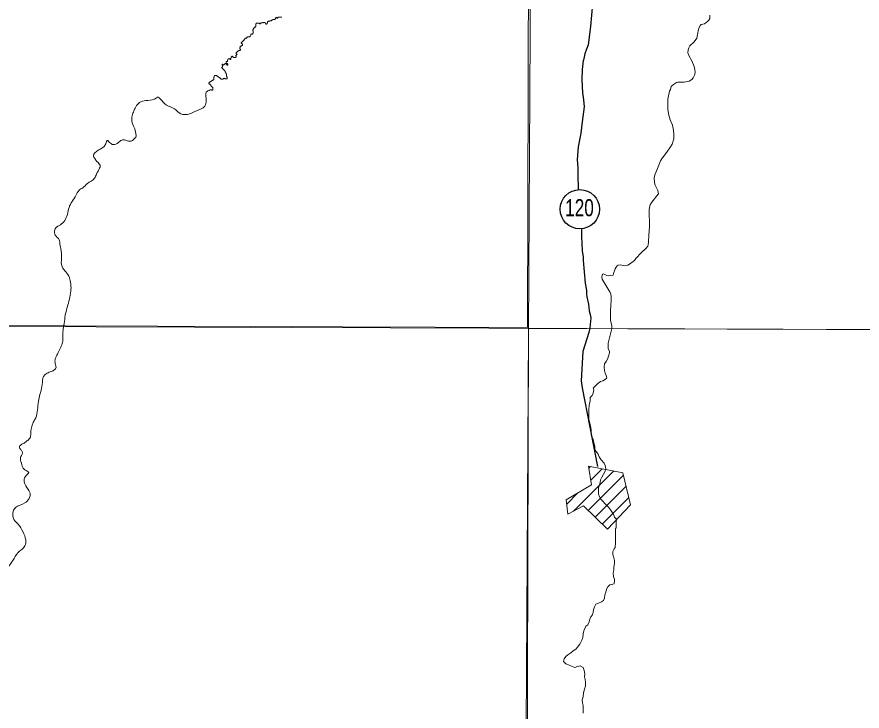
# Model space of a CAD drawing. Extents: x 553962 to 842807, y 8883888 to 9032388.
# Drawn here: x 605483 to 608938, y 8908325 to 8911165 of the extents above; entities that cross this region are included whole.
import ezdxf
from ezdxf.enums import TextEntityAlignment as Align

# ---------------------------------------------------------------- set-up
doc = ezdxf.new("R2010")
doc.units = 0
doc.header["$LTSCALE"] = 20
doc.layers.add('6', color=7, linetype='Continuous', lineweight=13)

msp = doc.modelspace()

# ---------------------------------------------------------------- linework, layer by layer
at = {"layer": '6'}
for p, q in [((574653.9, 8910009.29), (626625.69, 8909822.11)), ((607820.79, 8909318.7), (607828.11, 8909326.02)), ((607828.78, 8909270.13), (607875.43, 8909316.78)), ((607758.55, 8909143.32), (607922.76, 8909307.53)), ((607817.86, 8909146.06), (607962.46, 8909290.66)), ((607730.52, 8909171.86), (607776.5, 8909217.84)), ((607846.56, 8909118.2), (607973.3, 8909244.94)), ((607875.27, 8909090.34), (607984.15, 8909199.21))]:
    msp.add_line(p, q, dxfattribs=at)
for points in [[(607657.67, 8924743.35), (607574.22, 8909874.89), (607492.34, 8896026.67)], [(606523.31, 8911148.48), (606522.69, 8911148.69), (606521.67, 8911148.74), (606520.47, 8911148.8), (606519.25, 8911148.8), (606517.68, 8911148.53), (606516.48, 8911148.21), (606515.23, 8911147.91), (606513.83, 8911147.47), (606512.46, 8911147.32), (606510.89, 8911147.08), (606509.89, 8911146.46), (606508.86, 8911145.98)], [(606546.39, 8911159.84), (606543.77, 8911162.45), (606542.77, 8911162.38), (606541.9, 8911161.78), (606541.17, 8911160.88), (606540.7, 8911159.66), (606540.1, 8911158.26), (606539.45, 8911157.11), (606538.88, 8911156.06), (606538.33, 8911155.11), (606537.33, 8911154.64), (606536.23, 8911154.32), (606535.08, 8911154.32), (606533.88, 8911154.5), (606532.68, 8911154.21), (606531.49, 8911153.94), (606530.56, 8911153.41), (606529.59, 8911152.92), (606528.36, 8911152.97), (606526.87, 8911153.1), (606525.67, 8911153.11), (606524.94, 8911152.08), (606524.59, 8911151.11), (606524.17, 8911150.03), (606523.3, 8911148.48)], [(606565.15, 8911164.35), (606562.93, 8911163.56), (606559.98, 8911163.14), (606557.02, 8911163.14), (606553.16, 8911163.67), (606551.69, 8911163.82), (606550.56, 8911164.1), (606549.49, 8911164.1), (606549.29, 8911163), (606549.54, 8911161.9), (606549.79, 8911160.53), (606549.79, 8911159.48), (606548.84, 8911159), (606547.42, 8911159.41), (606546.39, 8911159.84)], [(608315.54, 8911171.73), (608315.61, 8911158.53), (608311.61, 8911151.94), (608307.35, 8911147.5), (608293.61, 8911136.89), (608279.96, 8911133.01), (608275.92, 8911129.45), (608268.82, 8911114.47), (608265.87, 8911093.15), (608261.93, 8911077.14), (608251.47, 8911062.72), (608234.36, 8911045.72), (608229.57, 8911037.8), (608226.74, 8911030.08), (608226.03, 8911018.33), (608229.52, 8911006.66), (608241.44, 8910984.96), (608251.55, 8910961.24), (608254.25, 8910949.42), (608255.3, 8910939.15), (608254.11, 8910930.39), (608252.74, 8910925.9), (608247.84, 8910915.8), (608242.31, 8910908.25), (608230.98, 8910902.21), (608210.39, 8910897.23), (608184.7, 8910897.91), (608178.91, 8910895.71), (608166.96, 8910888.78), (608158.11, 8910879.61), (608154.39, 8910868.28), (608151.07, 8910860.93), (608144.33, 8910828.85), (608143.31, 8910810.6), (608144.38, 8910797.99), (608143.86, 8910785.4), (608147.53, 8910763.33), (608153.66, 8910743.49), (608162.48, 8910721.36), (608166.26, 8910708.78), (608168.65, 8910688.23), (608168.26, 8910666.13), (608161.58, 8910644.74), (608155.1, 8910632.91), (608140.41, 8910611.88), (608121.6, 8910588.76), (608113.61, 8910576.05), (608102.12, 8910544.39), (608090.67, 8910519.25), (608088.69, 8910506.68), (608089.19, 8910486.11), (608091.86, 8910475.89), (608103.11, 8910454.43), (608105.72, 8910441.42), (608104.82, 8910439.14), (608078.56, 8910407.49), (608072.03, 8910396.61)], [(606478.63, 8911137.21), (606477.8, 8911136.54), (606476.1, 8911136.54), (606475.13, 8911136.85), (606474.48, 8911137.82), (606473.68, 8911138.48), (606472.66, 8911138.58), (606471.59, 8911138.58), (606470.49, 8911138.59), (606469.21, 8911138.47), (606468.04, 8911138.47), (606466.62, 8911138.48), (606465.27, 8911138.65), (606464.37, 8911139.36), (606463.22, 8911139.16), (606462.15, 8911138.69), (606461.12, 8911137.89), (606460.5, 8911136.95), (606460.3, 8911135.77), (606460.15, 8911134.3), (606460.15, 8911133.3), (606460.15, 8911132.3), (606460.15, 8911130.87), (606460, 8911129.07), (606459.7, 8911127.6), (606459.27, 8911126.57), (606458.82, 8911125.35), (606458.27, 8911124.3), (606457.32, 8911123.35), (606456.22, 8911122.41), (606455, 8911121.53), (606454.08, 8911120.76), (606453, 8911120.02), (606452.08, 8911119.57), (606451.2, 8911118.85), (606450.61, 8911117.92), (606449.58, 8911116.1), (606449.36, 8911115.13), (606448.76, 8911113.98), (606448.48, 8911112.88), (606448.16, 8911111.75), (606448.01, 8911110.56), (606448, 8911109.35), (606448, 8911108.18), (606448.1, 8911107.13), (606448.28, 8911106.08), (606448.33, 8911104.98), (606448.55, 8911103.63), (606448.8, 8911102.43), (606448.93, 8911101.35), (606448.97, 8911100.15), (606448.85, 8911098.2), (606448.5, 8911097.1), (606448.05, 8911096.18), (606447.3, 8911095.5), (606446.33, 8911095.03), (606445.03, 8911094.56), (606443.63, 8911094.57), (606442.63, 8911094.77), (606441.46, 8911094.65), (606440.23, 8911094.18), (606439.23, 8911093.53), (606438.73, 8911092.03), (606438.83, 8911090.88), (606437.66, 8911086.36)], [(606508.86, 8911145.98), (606508.11, 8911144.94), (606507.64, 8911143.76), (606507.51, 8911142.59), (606507.34, 8911141.36), (606506.96, 8911139.99), (606506.64, 8911138.62), (606506.51, 8911137.44), (606506.11, 8911136.49), (606505.39, 8911135.69), (606504.29, 8911135.2), (606503.19, 8911135.2), (606502.07, 8911135.53), (606501.17, 8911136.23), (606500.47, 8911137.11), (606499.75, 8911137.96), (606499.15, 8911138.79), (606498.4, 8911139.74), (606497.48, 8911140.57), (606496.63, 8911141.17), (606495.38, 8911141.75), (606494.21, 8911142.03), (606493.23, 8911142.41), (606492.03, 8911142.42), (606490.81, 8911142.24), (606489.61, 8911141.47), (606488.71, 8911140.78), (606487.71, 8911140.28), (606486.57, 8911140.33), (606485.29, 8911140.39), (606484.07, 8911140.44), (606482.9, 8911140.57), (606481.87, 8911140.45), (606480.45, 8911139.95), (606479.58, 8911139.41), (606479.13, 8911138.38), (606478.63, 8911137.21)], [(606437.66, 8911086.36), (606436.73, 8911085.74), (606435.71, 8911085.06), (606434.81, 8911084.34), (606433.89, 8911083.7), (606432.61, 8911083.1), (606431.22, 8911083), (606429.59, 8911082.81), (606428.37, 8911082.76), (606427, 8911082.72), (606425.52, 8911082.42), (606424.45, 8911082.08), (606423.53, 8911081.43), (606423.23, 8911080.43), (606423.1, 8911079.36), (606422.75, 8911078.18), (606422.05, 8911077.23), (606419.88, 8911077.27), (606417.17, 8911077.7), (606411.51, 8911071.74), (606411.19, 8911070.54), (606411.44, 8911069.57), (606410.74, 8911068.72), (606409.66, 8911068.2), (606408.64, 8911067.83), (606408.49, 8911066.73), (606406.72, 8911065.4)], [(606406.72, 8911065.4), (606400.11, 8911059.18), (606399.49, 8911057.18), (606401.77, 8911054.97), (606403.27, 8911054.79), (606404.42, 8911054.74), (606405.09, 8911053.78), (606405.44, 8911052.76), (606405.69, 8911051.63), (606405.64, 8911050.48), (606405.44, 8911049.31), (606404.84, 8911048.41), (606403.99, 8911047.84), (606403.19, 8911047.19), (606402.04, 8911046.89), (606400.94, 8911046.25), (606400.09, 8911045.55), (606399.22, 8911044.9), (606398.17, 8911045.05), (606397.15, 8911045.28), (606396.15, 8911044.64), (606395.7, 8911043.74), (606395.6, 8911042.51), (606395.5, 8911041.24), (606395.17, 8911039.69), (606395, 8911038.41), (606394.95, 8911036.91), (606394.94, 8911035.74), (606394.94, 8911034.71), (606395.62, 8911033.73), (606396.14, 8911032.86), (606396.49, 8911031.76), (606396.49, 8911030.71), (606396.49, 8911029.33), (606396.19, 8911028.16), (606395.54, 8911027.33), (606394.49, 8911027.14), (606393.42, 8911026.89), (606391.87, 8911026.72), (606390.8, 8911026.57), (606389.32, 8911026.33), (606388.2, 8911025.96), (606387.15, 8911025.31), (606386.03, 8911024.59), (606385.3, 8911023.57), (606384.58, 8911022.59), (606383.95, 8911021.7), (606383.08, 8911020.52), (606382.15, 8911019.83), (606381.23, 8911019.2), (606380.38, 8911018.43), (606379.78, 8911017.28), (606379.58, 8911015.88), (606379.73, 8911014.83), (606380.43, 8911013.48), (606381.4, 8911012.88), (606382.55, 8911012.77), (606383.25, 8911011.95), (606382.6, 8911011.1), (606381.78, 8911010.47), (606380.68, 8911010.13), (606379.78, 8911009.43), (606378.95, 8911008.51), (606378.65, 8911007.33), (606378.6, 8911006.11)], [(606344.24, 8910987.34), (606343.59, 8910982.87), (606342.52, 8910982.42), (606341.37, 8910982.53), (606341.09, 8910982.73), (606339.85, 8910982.58), (606338.8, 8910982.16), (606338.62, 8910981.01), (606338.62, 8910979.64)], [(606338.62, 8910979.64), (606339.89, 8910976.11), (606340.44, 8910975.08), (606341.17, 8910974.28), (606342.06, 8910973.75), (606343.76, 8910973.09), (606344.71, 8910972.64), (606345.63, 8910971.96), (606345.68, 8910970.94), (606345.68, 8910969.84), (606345.38, 8910968.81), (606344.91, 8910967.81)], [(606346.51, 8910992.79), (606346.44, 8910992.24), (606345.97, 8910991.24), (606345.34, 8910990.19), (606344.77, 8910989.27), (606344.77, 8910988.22), (606344.24, 8910987.34)], [(606351.56, 8910993.32), (606350.49, 8910993.18), (606349.26, 8910993.18), (606348.11, 8910993.16), (606346.5, 8910992.75)], [(606362.89, 8911004.02), (606362.13, 8911003.56), (606361.15, 8911002.64), (606360, 8911001.3), (606359.58, 8911000.37), (606359.2, 8910999.4), (606358.73, 8910998.37), (606358.45, 8910997.17), (606358.3, 8910997.05), (606358.25, 8910994.1), (606358.25, 8910993.05), (606358.15, 8910992.05), (606357.63, 8910990.95), (606356.68, 8910990.38), (606355.58, 8910990.08), (606355, 8910990.96), (606354.83, 8910992.01), (606355.08, 8910993.11), (606355.21, 8910994.11), (606354.43, 8910994.86), (606353.31, 8910994.44), (606352.43, 8910993.84), (606351.56, 8910993.32)], [(606378.6, 8911006.11), (606378.8, 8911005.08), (606378.93, 8911003.96), (606378.93, 8911002.71), (606378.88, 8911001.66), (606378.55, 8911000.66), (606377.85, 8910999.86), (606376.93, 8910999.19), (606375.78, 8910998.84), (606374.56, 8910998.55), (606373.31, 8910998.25), (606371.68, 8910998.26), (606370.71, 8910998.63), (606369.81, 8910999.16), (606368.94, 8911000.12), (606367.92, 8911000.54), (606366.19, 8911000.67), (606365.19, 8911001.43), (606364.45, 8911002.11), (606363.87, 8911003.03), (606362.8, 8911003.97)], [(606344.91, 8910967.81), (606344.36, 8910966.89), (606342.98, 8910966.82), (606341.99, 8910967.15), (606341.61, 8910968.12), (606341.36, 8910969.12), (606340.84, 8910970.15), (606340.39, 8910971.33), (606339.39, 8910972.48), (606338.62, 8910973.13), (606337.62, 8910973.46), (606336.57, 8910973.59), (606335.27, 8910973.45), (606334.22, 8910973.2), (606333.43, 8910972.53), (606332.33, 8910971.81), (606331.43, 8910970.66), (606330.73, 8910969.69), (606329.9, 8910968.76), (606329.18, 8910968.04), (606328.16, 8910967.74), (606327.16, 8910967.8), (606326.23, 8910968.25), (606325.53, 8910969.08), (606324.84, 8910969.96), (606324.24, 8910970.83), (606323.19, 8910971.26), (606322.19, 8910970.44), (606322.39, 8910969.34), (606322.71, 8910968.26), (606323.06, 8910967.26), (606323.21, 8910966.21), (606323.51, 8910964.81), (606323.64, 8910963.76), (606323.63, 8910962.46), (606323.48, 8910961.21), (606323.18, 8910960.18), (606322.29, 8910959.49), (606321.39, 8910958.84), (606320.89, 8910957.94), (606321.01, 8910956.31), (606321.51, 8910955.14), (606322.28, 8910954.43), (606323.28, 8910953.48), (606324.33, 8910952.68), (606325.3, 8910952.1), (606326.28, 8910951.45), (606327, 8910950.47), (606327.77, 8910949.49), (606328.52, 8910948.56), (606329.22, 8910947.63), (606330.14, 8910946.76), (606330.77, 8910945.85), (606331.69, 8910944.93), (606332.61, 8910944.25), (606333.59, 8910943.24), (606334.06, 8910942.27), (606334.51, 8910941.24), (606335.06, 8910939.84), (606335.83, 8910938.78), (606336.43, 8910937.91), (606336.73, 8910936.91), (606336.98, 8910935.88), (606337.28, 8910934.78), (606340.01, 8910930.94)], [(606307.73, 8910917.55), (606305.96, 8910919.61), (606304.79, 8910920.71), (606304.07, 8910921.61), (606303.17, 8910922.24), (606302.15, 8910922.77), (606300.97, 8910923.4), (606300.22, 8910924.13), (606299.38, 8910925), (606298.05, 8910924.98), (606297.05, 8910924.76), (606296.06, 8910924.54), (606294.93, 8910924.54), (606293.86, 8910924.9), (606292.81, 8910925.05), (606291.44, 8910925.21), (606290.26, 8910924.78), (606289.51, 8910922.56), (606289.34, 8910921.04), (606289.19, 8910919.91), (606288.66, 8910918.76), (606288.24, 8910917.74), (606287.94, 8910916.66), (606288.06, 8910915.66), (606288.19, 8910914.49), (606288.46, 8910912.91), (606288.58, 8910911.79), (606288.71, 8910910.59), (606288.66, 8910909.59), (606288.21, 8910908.69), (606287.41, 8910908.06), (606286.46, 8910907.54), (606285.54, 8910907.02), (606284.59, 8910906.1), (606283.84, 8910905.38), (606282.64, 8910904.65), (606281.32, 8910904.01), (606280.27, 8910903.34), (606279.04, 8910902.72), (606278.02, 8910902.22), (606276.82, 8910901.85), (606275.47, 8910900.9), (606274.62, 8910900.18), (606273.82, 8910899.48), (606272.9, 8910898.76), (606271.53, 8910898.04), (606270.45, 8910897.32), (606269.6, 8910896.55), (606268.88, 8910895.57), (606268.03, 8910894.83), (606267.48, 8910893.95), (606267.46, 8910892.93), (606267.83, 8910891.88), (606268.58, 8910890.9), (606269.63, 8910890.27), (606270.6, 8910889.89), (606271.67, 8910889.31), (606272.8, 8910888.71), (606273.69, 8910888.05), (606274.44, 8910887.33), (606274.94, 8910886.42), (606275.24, 8910885.42), (606275.77, 8910884.5), (606276.06, 8910883.37), (606276.64, 8910882.29)], [(606340.01, 8910930.94), (606339.95, 8910929.49), (606339.85, 8910928.32), (606339.8, 8910927.17), (606339.45, 8910924.44), (606339.84, 8910923.37), (606340.44, 8910922.29), (606340.94, 8910921.34), (606341.22, 8910920.01), (606341.59, 8910919.03), (606342.11, 8910917.88), (606342.44, 8910916.93), (606342.76, 8910915.95), (606343.04, 8910914.7), (606343.04, 8910913.65), (606342.71, 8910912.53), (606341.64, 8910911.61), (606340.41, 8910911.34), (606339.29, 8910911.29), (606338.24, 8910911.64), (606336.74, 8910911.45), (606335.45, 8910911.3), (606334.4, 8910911.81), (606333.47, 8910912.31), (606332.4, 8910912.94), (606330.9, 8910913.47), (606329.85, 8910913.32), (606328.9, 8910913), (606327.68, 8910912.6), (606326.71, 8910912.31), (606325.76, 8910911.66), (606324.51, 8910910.64), (606323.41, 8910909.89), (606321.94, 8910909.77), (606320.69, 8910909.63), (606319.52, 8910909.51), (606318.07, 8910909.91), (606317.12, 8910910.41), (606316.1, 8910911.34), (606315.07, 8910912.3), (606314.13, 8910913.35), (606313.5, 8910914.25), (606312.68, 8910915.33), (606311.88, 8910916.21), (606311.01, 8910916.96), (606309.93, 8910917.29), (606307.73, 8910917.55)], [(606276.64, 8910882.29), (606277.21, 8910881.14), (606278.01, 8910880.44), (606278.91, 8910879.73), (606279.88, 8910879.33), (606280.78, 8910878.78), (606281.93, 8910878.15), (606282.83, 8910877.67), (606283.48, 8910876.72), (606283.75, 8910875.74), (606283.75, 8910874.72), (606283.75, 8910873.67), (606283.75, 8910872.42), (606283.87, 8910870.94), (606283.87, 8910869.59), (606283.87, 8910868.49), (606283.82, 8910867.46), (606283.62, 8910866.29), (606282.8, 8910865.57), (606281.8, 8910865.47), (606280.72, 8910865.6), (606279.68, 8910865.6), (606278.65, 8910865.86), (606277.63, 8910865.86), (606273.75, 8910865.93)], [(608072.03, 8910396.61), (608069.62, 8910387.12), (608068.06, 8910373.76), (608068.35, 8910308.21), (608067.63, 8910288.42), (608066.22, 8910273.5), (608065.11, 8910243.44), (608063.49, 8910232.33), (608061.9, 8910226.97), (608055.7, 8910219), (608035.74, 8910200.63), (608012.49, 8910176.3), (608007.66, 8910168.55), (607987.34, 8910153.61), (607980.83, 8910149.92), (607970.65, 8910147.25), (607961.93, 8910147.29), (607948.54, 8910151.31), (607941.13, 8910148.68), (607937.31, 8910146.51), (607932.09, 8910141.45), (607928.46, 8910134.88), (607921.33, 8910114.87), (607920.78, 8910110.12), (607919.86, 8910108.9), (607911.61, 8910106.39), (607900.45, 8910105.56), (607894.37, 8910107.15), (607884.34, 8910112.39), (607879.33, 8910113.23), (607877.08, 8910112.31), (607875.27, 8910108.43), (607873.83, 8910098.7), (607875.04, 8910091.52), (607907.76, 8910037.42), (607910.93, 8910030.12), (607911.9, 8910021.71)], [(607911.9, 8910021.71), (607911.94, 8910002.71), (607911.94, 8910002.71), (607910.62, 8909987.8), (607909.46, 8909957.73), (607910.2, 8909924.57), (607914.39, 8909900.9), (607915.46, 8909889.87), (607900.16, 8909830.51)], [(607900.16, 8909830.51), (607900.09, 8909819.31), (607900.02, 8909809.12), (607905.02, 8909796.87), (607905.61, 8909789.54)], [(607905.85, 8909790.3), (607901.83, 8909777.54), (607896.65, 8909764.33), (607892.52, 8909755.19), (607884.75, 8909745.43), (607883.4, 8909732.42), (607884.75, 8909718.52), (607888.12, 8909707.35), (607892.13, 8909698.15), (607894.87, 8909687.9)], [(607894.45, 8909687.54), (607888.97, 8909682.9), (607877.74, 8909676.85), (607868.56, 8909672.84), (607858.34, 8909665.77), (607851.17, 8909658.68), (607839.46, 8909647.11)], [(607839.25, 8909647.81), (607841.54, 8909639.98), (607838.39, 8909625.74), (607834.26, 8909616.6), (607826.06, 8909607.49), (607825.96, 8909593.23), (607821.78, 8909577.98), (607821.63, 8909556.59), (607820.52, 8909542.34), (607820.45, 8909532.15), (607820.36, 8909519.93), (607824.35, 8909508.7), (607827.29, 8909492.39), (607830.23, 8909476.08), (607830.16, 8909465.89), (607831.11, 8909455.7), (607834.09, 8909445.5), (607838.09, 8909436.31), (607842.07, 8909423.04), (607846.04, 8909408.76), (607845.97, 8909398.58), (607848.95, 8909388.37), (607858.04, 8909379.15), (607863.04, 8909365.88), (607872.1, 8909352.58), (607884.21, 8909339.27), (607888.22, 8909330.08), (607890.16, 8909316.83), (607887.02, 8909303.61), (607880.85, 8909294.48), (607874.66, 8909282.29), (607868.48, 8909271.13), (607867.4, 8909260.95), (607864.27, 8909250.78), (607861.14, 8909238.58), (607861.05, 8909225.34), (607859.94, 8909213.13), (607863.94, 8909201.9), (607869.98, 8909192.7), (607878.05, 8909183.48), (607885.12, 8909176.31), (607893.2, 8909168.11), (607901.28, 8909159.91), (607909.34, 8909148.66), (607915.39, 8909140.47)], [(607915.39, 8909140.47), (607922.44, 8909130.25), (607926.43, 8909119.02), (607933.48, 8909109.81), (607933.4, 8909097.59), (607933.32, 8909086.39), (607933.24, 8909075.18), (607929.22, 8909068.94)], [(607928.51, 8908994.81), (607924.69, 8908988.89), (607918.51, 8908977.73), (607918.43, 8908965.51), (607923.42, 8908952.23), (607926.4, 8908942.03), (607926.32, 8908929.81), (607923.15, 8908913.53), (607923.08, 8908902.33), (607919.95, 8908891.15), (607921.87, 8908874.84), (607925.87, 8908864.63), (607925.8, 8908854.45), (607923.86, 8908845.1)], [(607924.18, 8908846.62), (607906.38, 8908841.32), (607898.19, 8908833.23), (607893.04, 8908824.09), (607889.9, 8908811.89), (607885.75, 8908800.71), (607885.66, 8908787.47), (607881.52, 8908777.31), (607872.33, 8908772.28), (607861.11, 8908767.25), (607849.89, 8908763.25), (607843.71, 8908752.08), (607839.56, 8908739.89), (607838.47, 8908729.71), (607835.35, 8908719.54), (607829.18, 8908710.41), (607825.05, 8908701.27), (607821.93, 8908691.11), (607816.76, 8908678.92), (607808.58, 8908672.86), (607804.44, 8908662.7), (607800.31, 8908653.56), (607797.17, 8908641.35), (607797.07, 8908626.08), (607791.9, 8908614.9), (607784.68, 8908599.67), (607774.41, 8908586.49), (607767.25, 8908579.41), (607757.02, 8908572.34), (607747.81, 8908564.25), (607735.54, 8908555.16), (607726.35, 8908549.1), (607720.17, 8908538.96), (607718.07, 8908528.79), (607727.15, 8908518.55), (607737.3, 8908514.41), (607749.47, 8908509.24), (607763.67, 8908504.06), (607774.89, 8908508.07), (607786.1, 8908511.05), (607797.24, 8908503.86), (607802.24, 8908491.6), (607805.2, 8908478.35), (607803.08, 8908466.14), (607806.05, 8908454.92), (607806.99, 8908443.71), (607806.89, 8908429.45), (607802.73, 8908415.22), (607798.55, 8908399.96), (607797.42, 8908383.68), (607794.29, 8908371.47), (607795.22, 8908359.24), (607797.18, 8908349.05), (607798.13, 8908338.86), (607798.06, 8908328.67), (607797.97, 8908316.45)]]:
    msp.add_lwpolyline(points, dxfattribs=at)
for points in [[(607600.79, 8920952.39), (596639.85, 8920989.8), (596608.84, 8909934.36), (607569.77, 8909894.88)], [(618535.25, 8909853.32), (607574.31, 8909890.72), (607543.3, 8898835.28), (618504.23, 8898795.81)], [(607819.31, 8909327.74), (607832.01, 8909250.51), (607728.79, 8909189.77), (607734.49, 8909130.68), (607798.87, 8909164.49), (607897.06, 8909069.19), (607991.4, 8909168.63), (607960.19, 8909300.22)]]:
    msp.add_lwpolyline(points, close=True, dxfattribs=at)
at = {"layer": '6', "lineweight": 25}
for points in [[(607784.93, 8911999.57), (607782.07, 8911967.5), (607781.29, 8911929.48), (607788, 8911886.91), (607792.45, 8911839.47), (607788.32, 8911760.36), (607788.88, 8911720.87), (607793.11, 8911695.9), (607802.04, 8911666.82), (607810.54, 8911630.63), (607820.1, 8911605.62), (607832.4, 8911579.04), (607837.33, 8911566.1), (607839.48, 8911553.21), (607843.68, 8911515.34), (607845.85, 8911475.84), (607845.06, 8911393.02), (607845.39, 8911323.56), (607839.94, 8911277.19), (607839.06, 8911261.73), (607839.24, 8911246.25), (607835.68, 8911217.87), (607827.19, 8911125.43)], [(607827.19, 8911125.43), (607818.35, 8911050.13), (607817.28, 8911045.7), (607811.11, 8911032.11), (607804.18, 8911013.71), (607798.72, 8910987.69)], [(607798.72, 8910987.69), (607798.42, 8910986.26), (607793.57, 8910949.11), (607793.06, 8910907.55), (607795.54, 8910854.19), (607799.32, 8910825.82), (607801.38, 8910796.65), (607794, 8910735.73)], [(607794, 8910735.73), (607788.36, 8910689.18), (607776.77, 8910633.27), (607773.29, 8910579.94), (607775.88, 8910548.19), (607775.87, 8910521.98), (607777.94, 8910458.78)], [(607790.87, 8910298.46), (607791.21, 8910291.97), (607790.88, 8910265.3), (607792.94, 8910237.78), (607794.03, 8910207.76), (607797.21, 8910181.92), (607797.79, 8910168.17), (607805.9, 8910075.32), (607811.66, 8910045.19), (607812, 8910030.62), (607813.2, 8910020.29), (607819.18, 8909989.35), (607822.23, 8909962.68), (607826.43, 8909948.07), (607828.55, 8909934.32), (607828.07, 8909919.75), (607824.74, 8909893.07), (607821.44, 8909873.29)], [(607821.44, 8909873.29), (607797, 8909796.06), (607789.43, 8909676.87), (607793.39, 8909647.32), (607855.85, 8909325.57)]]:
    msp.add_lwpolyline(points, dxfattribs=at)
msp.add_circle((607784.39, 8910378), 80.26, dxfattribs=at)
at = {"layer": '6'}
for points in [[(606273.75, 8910865.93), (606257.21, 8910856.22), (606257.21, 8910822.13), (606251.2, 8910800.06), (606217.12, 8910780.01), (606181.04, 8910765.97), (606152.97, 8910767.97), (606126.91, 8910788.03), (606094.83, 8910804.08), (606068.77, 8910830.15), (606060.95, 8910836.57), (606044.92, 8910828.54), (606009.63, 8910822.93), (605983.97, 8910814.1), (605969.54, 8910797.26), (605959.12, 8910775.59), (605953.5, 8910753.93), (605956.71, 8910724.25), (605967.14, 8910700.18), (605969.54, 8910684.94), (605971.14, 8910676.91), (605966.33, 8910669.69), (605955.11, 8910659.26), (605943.88, 8910656.06), (605927.04, 8910660.87), (605911.81, 8910660.87), (605898.17, 8910650.44), (605876.52, 8910642.42), (605862.09, 8910651.24), (605852.47, 8910659.26), (605847.66, 8910649.64), (605839.64, 8910635.2), (605817.99, 8910620.76), (605802.75, 8910610.33), (605795.53, 8910596.69), (605797.94, 8910591.07), (605814.78, 8910568.61)], [(605814.78, 8910568.61), (605823.6, 8910554.17), (605821.19, 8910546.14), (605808.36, 8910522.07), (605800.35, 8910505.23), (605771.48, 8910482.76), (605752.23, 8910465.92), (605737, 8910455.49), (605724.17, 8910434.63), (605708.93, 8910409.76), (605696.1, 8910385.69), (605689.69, 8910356.81), (605678.46, 8910331.94), (605660.82, 8910314.29), (605641.57, 8910301.45), (605636.76, 8910285.41), (605639.97, 8910272.57), (605656.01, 8910252.51), (605659.22, 8910234.06), (605665.63, 8910197.16), (605668.84, 8910140.19), (605678.46, 8910126.56), (605695.3, 8910104.89), (605699.31, 8910092.86), (605704.12, 8910063.98), (605702.52, 8910035.1), (605695.3, 8910001.4), (605680.87, 8909944.44), (605676.06, 8909910.74), (605670.44, 8909860.44), (605671.24, 8909848.41), (605668.04, 8909828.35), (605660.02, 8909809.1), (605648.79, 8909785.83), (605639.97, 8909766.58), (605639.97, 8909746.52), (605642.38, 8909728.07), (605631.15, 8909717.64), (605615.11, 8909711.22), (605599.08, 8909701.59), (605590.26, 8909691.16), (605587.85, 8909678.33), (605583.84, 8909644.63), (605577.43, 8909620.56), (605571.81, 8909592.48), (605567, 8909557.18), (605559.78, 8909525.09), (605551.77, 8909509.85), (605545.35, 8909494.61), (605540.54, 8909473.75), (605538.94, 8909449.68), (605533.32, 8909438.45), (605520.49, 8909428.02), (605509.27, 8909420), (605497.24, 8909413.58)], [(605497.24, 8909413.58), (605493.23, 8909402.35), (605497.24, 8909396.73), (605505.26, 8909387.1), (605504.45, 8909375.87), (605498.84, 8909367.05), (605499.64, 8909346.19), (605507.66, 8909321.32), (605515.68, 8909312.49), (605531.54, 8909301.97), (605517.61, 8909284.95), (605512.97, 8909263.28), (605528.45, 8909232.32), (605537.74, 8909210.65), (605533.09, 8909195.17), (605516.07, 8909176.6), (605477.37, 8909158.02), (605468.08, 8909142.54), (605471.18, 8909108.49), (605486.66, 8909091.46), (605508.33, 8909057.41), (605519.16, 8909026.45), (605516.07, 8909001.69), (605488.2, 8908973.82), (605466.53, 8908941.32), (605435.11, 8908893.33), (605415.92, 8908841.33), (605389.91, 8908820.27), (605356.48, 8908796.13), (605331.09, 8908770.12), (605303.85, 8908752.79), (605276.61, 8908724.31), (605240.7, 8908689.01), (605218.41, 8908671.68), (605191.79, 8908661.77), (605163.92, 8908650.63), (605124.92, 8908630.81), (605093.34, 8908612.86), (605095.82, 8908620.29), (605095.2, 8908634.53), (605089.01, 8908649.39), (605076, 8908653.72), (605050.62, 8908663.01), (605038.86, 8908674.77), (605035.76, 8908683.44), (605017.8, 8908684.68), (604994.28, 8908697.06), (604979.42, 8908708.21), (604969.51, 8908720.59), (604963.94, 8908739.78), (604950.94, 8908776.31), (604946.6, 8908786.84), (604936.7, 8908791.17), (604926.17, 8908797.37), (604914.83, 8908802.56)], [(607929.64, 8909069.6), (607930.48, 8909038.78), (607930.48, 8909019.86), (607928.29, 8908994.47)]]:
    msp.add_spline(points, degree=3, dxfattribs=at)

# ---------------------------------------------------------------- texts
at = {"layer": '6', "width": 0.75}
msp.add_text('120', height=70, dxfattribs=at).set_placement((607782.84, 8910349.31), align=Align.CENTER)

doc.saveas('drawing.dxf')
